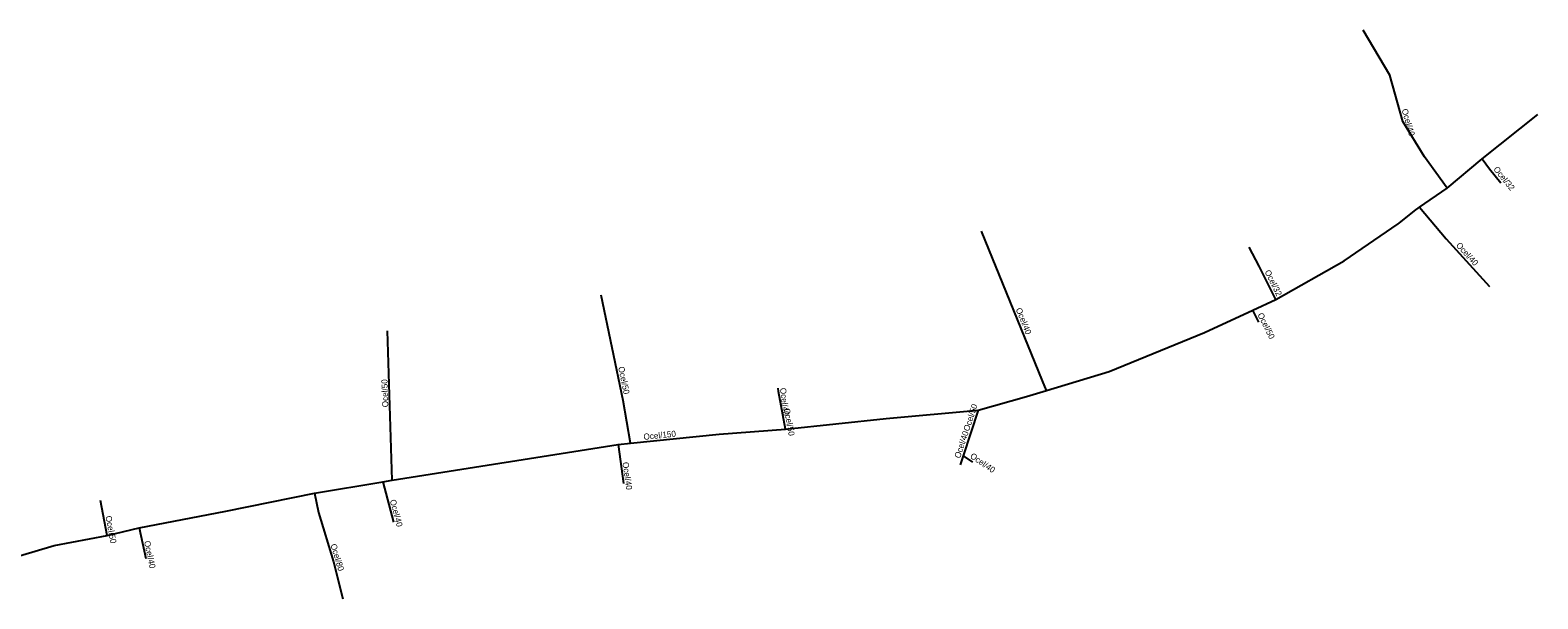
# Model space of a CAD drawing. Extents: x -750089 to -749346, y -965846 to -965561.
# Drawn here: x -749715.8 to -749529.7, y -965814 to -965743.8 of the extents above; entities that cross this region are included whole.
import ezdxf

# ---------------------------------------------------------------- set-up
doc = ezdxf.new("R2010")
doc.units = 0
for name, color, linetype in [('14', 7, 'Continuous'), ('18', 7, 'Continuous'), ('20', 7, 'Continuous')]:
    doc.layers.add(name, color=color, linetype=linetype)

msp = doc.modelspace()

# ---------------------------------------------------------------- linework, layer by layer
at = {"layer": '14'}
for points in [[(-749540.93, -965763.31), (-749543.71, -965759.44), (-749546.39, -965755.05), (-749548, -965749.36), (-749551.3, -965743.78)], [(-749598.8, -965790.72), (-749592.84, -965789.02), (-749590.39, -965788.3), (-749582.65, -965785.95), (-749570.88, -965781.12), (-749564.92, -965778.37), (-749562.07, -965777.06), (-749553.63, -965772.28), (-749546.95, -965767.7), (-749546.84, -965767.62), (-749544.94, -965766.11), (-749544.35, -965765.64), (-749540.93, -965763.31), (-749536.59, -965759.69), (-749529.71, -965754.21)], [(-749536.59, -965759.69), (-749535.67, -965760.91), (-749534.28, -965762.64)], [(-749544.35, -965765.64), (-749541.02, -965769.56), (-749535.68, -965775.44)], [(-749590.39, -965788.3), (-749590.88, -965787.07), (-749598.39, -965768.6)], [(-749562.07, -965777.06), (-749564.11, -965772.91), (-749565.34, -965770.59)], [(-749641.73, -965794.77), (-749642.65, -965789.52), (-749645.33, -965776.49)], [(-749564.18, -965779.86), (-749564.92, -965778.37)], [(-749671.13, -965799.36), (-749671.71, -965780.92)], [(-749623.44, -965788.42), (-749623.49, -965787.98)], [(-749622.58, -965793.05), (-749623.44, -965788.42)], [(-749680.74, -965800.98), (-749672.31, -965799.55), (-749671.13, -965799.36), (-749643.25, -965794.97), (-749641.73, -965794.77), (-749630.79, -965793.67), (-749622.58, -965793.05), (-749610.15, -965791.75), (-749598.8, -965790.72)], [(-749598.8, -965790.72), (-749600.67, -965796.35)], [(-749643.25, -965794.97), (-749642.58, -965799.76)], [(-749600.67, -965796.35), (-749601.04, -965797.48)], [(-749672.31, -965799.55), (-749670.98, -965804.55)], [(-749721.48, -965809.99), (-749712.85, -965807.44), (-749706.33, -965806.2), (-749702.36, -965805.23), (-749691.66, -965803.18), (-749680.74, -965800.98)], [(-749706.33, -965806.2), (-749707.15, -965801.86)], [(-749680.74, -965800.98), (-749680.25, -965803.33), (-749678.39, -965809.44), (-749677.23, -965814.01)], [(-749702.36, -965805.23), (-749701.57, -965809.03)]]:
    msp.add_lwpolyline(points, dxfattribs=at)
at = {"layer": '18'}
msp.add_lwpolyline([(-749600.67, -965796.35), (-749599.5, -965797.15)], dxfattribs=at)

# ---------------------------------------------------------------- texts
at = {"layer": '20'}
for s, rotation, p in [('Ocel/40', 285.799, (-749546.54, -965753.61)), ('Ocel/32', 308.7808, (-749535.25, -965760.98)), ('Ocel/40', 312.2664, (-749539.88, -965770.4)), ('Ocel/32', 296.1772, (-749563.47, -965773.61)), ('Ocel/40', 292.1342, (-749594.19, -965778.25)), ('Ocel/50', 296.3181, (-749564.35, -965778.92)), ('Ocel/50', 91.788, (-749671.62, -965790.34)), ('Ocel/50', 281.6086, (-749643.25, -965785.41)), ('Ocel/40', 276.4831, (-749623.27, -965788)), ('Ocel/50', 280.5225, (-749622.81, -965790.54)), ('Ocel/50', 71.6689, (-749599.95, -965793.38)), ('Ocel/150', 5.7417, (-749640.08, -965794.38)), ('Ocel/40', 71.6742, (-749601.05, -965796.72)), ('Ocel/40', 325.4102, (-749599.88, -965796.55)), ('Ocel/40', 277.9626, (-749642.72, -965797.17)), ('Ocel/40', 284.8951, (-749671.44, -965801.85)), ('Ocel/50', 280.6993, (-749706.54, -965803.83)), ('Ocel/40', 281.7303, (-749701.77, -965806.93)), ('Ocel/80', 286.9312, (-749678.77, -965807.34))]:
    msp.add_text(s, height=0.75, rotation=rotation, dxfattribs=at).set_placement(p)

doc.saveas('drawing.dxf')
